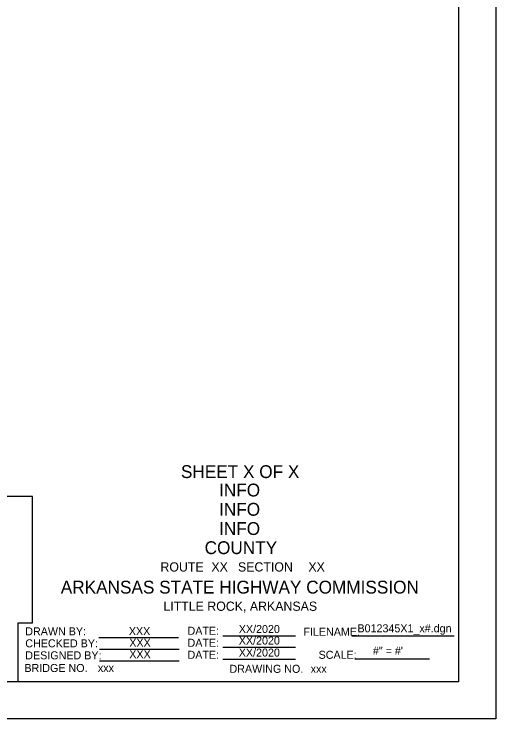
# Model space of a CAD drawing. Extents: x 16 to 1228740, y 11 to 152440.
# Drawn here: x 17.864 to 18.49, y 10.709 to 11.626 of the extents above; entities that cross this region are included whole.
import ezdxf

# ---------------------------------------------------------------- set-up
doc = ezdxf.new("R2010")
doc.units = 0
for name, color, linetype in [('B_Copy In', 7, 'Continuous'), ('B_County and Route', 7, 'Continuous'), ('B_Text', 7, 'Continuous'), ('B_Title Text', 7, 'Continuous'), ('R_Border', 7, 'Continuous'), ('R_No Plot', 7, 'Continuous')]:
    doc.layers.add(name, color=color, linetype=linetype)

msp = doc.modelspace()

# ---------------------------------------------------------------- linework, layer by layer
at = {"layer": 'B_Text'}
for p, q in [((18.13559, 10.81765), (18.23009, 10.81765)), ((18.30318, 10.81765), (18.43623, 10.81765)), ((17.97449, 10.81515), (18.07809, 10.81515)), ((17.97509, 10.80015), (18.07869, 10.80015)), ((18.13559, 10.80265), (18.23009, 10.80265)), ((18.13559, 10.80265), (18.23009, 10.80265)), ((17.97509, 10.78515), (18.07869, 10.78515)), ((18.13559, 10.78703), (18.23009, 10.78703)), ((18.30706, 10.78765), (18.40419, 10.78765))]:
    msp.add_line(p, q, dxfattribs=at)
at = {"layer": 'R_Border'}
for q in [(18.44221, 12.49475), (15.78327, 10.75755)]:
    msp.add_line((18.44221, 10.75755), q, dxfattribs=at)
msp.add_lwpolyline([(15.65694, 12.54282), (18.49027, 12.54282), (18.49027, 10.70949), (15.65694, 10.70949)], close=True, dxfattribs=at)
at = {"layer": 'R_No Plot'}
for p, q in [((17.888, 10.99864), (17.47349, 10.99864)), ((17.888, 10.83424), (17.888, 10.99864)), ((17.86946, 10.83424), (17.888, 10.83424)), ((17.86946, 10.75755), (17.86946, 10.83424))]:
    msp.add_line(p, q, dxfattribs=at)

# ---------------------------------------------------------------- texts
at = {"layer": 'B_Copy In'}
for s, height, p in [('SHEET X OF X', 0.0167, (18.08103, 11.02272)), ('INFO', 0.0167, (18.13057, 10.99878)), ('INFO', 0.0167, (18.13057, 10.97373)), ('INFO', 0.0167, (18.13057, 10.94868)), ('XXX', 0.0104, (18.01335, 10.81846)), ('XX/2020', 0.0104, (18.15625, 10.82119)), ('B012345X1_x#.dgn', 0.0104, (18.31045, 10.8221)), ('XX/2020', 0.0104, (18.15625, 10.80619)), ('XXX', 0.0104, (18.01395, 10.80346)), ('XXX', 0.0104, (18.01395, 10.78846)), ('XX/2020', 0.0104, (18.15625, 10.79057)), ('#" = #\'', 0.0104, (18.3305, 10.79302)), ('xxx', 0.010417, (17.97312, 10.7706)), ('xxx', 0.010417, (18.24962, 10.76944))]:
    msp.add_text(s, height=height, dxfattribs=at).set_placement(p)
at = {"layer": 'B_County and Route'}
for s, height, p in [('COUNTY', 0.0167, (18.11181, 10.92383)), ('XX', 0.012, (18.12061, 10.90115)), ('XX', 0.012, (18.24664, 10.90115))]:
    msp.add_text(s, height=height, dxfattribs=at).set_placement(p)
at = {"layer": 'B_Text'}
for s, height, p in [('DRAWN BY:', 0.010417, (17.87879, 10.8182)), ('DATE:', 0.010417, (18.08959, 10.8189)), ('FILENAME:', 0.010417, (18.24018, 10.81765)), ('CHECKED BY:', 0.0104166, (17.87879, 10.80257)), ('DATE:', 0.010417, (18.08959, 10.80328)), ('DESIGNED BY:', 0.0104166, (17.87879, 10.78695)), ('DATE:', 0.010417, (18.08959, 10.78765)), ('SCALE:', 0.010417, (18.25989, 10.78765)), ('BRIDGE NO.', 0.010417, (17.87767, 10.77048)), ('DRAWING NO.', 0.0104166, (18.14412, 10.76942))]:
    msp.add_text(s, height=height, dxfattribs=at).set_placement(p)
at = {"layer": 'B_Title Text'}
for s, height, p in [('ROUTE          SECTION ', 0.012, (18.0544, 10.90115)), ('ARKANSAS STATE HIGHWAY COMMISSION', 0.0167, (17.92492, 10.8725)), ('LITTLE ROCK, ARKANSAS', 0.012, (18.05823, 10.85007))]:
    msp.add_text(s, height=height, dxfattribs=at).set_placement(p)

doc.saveas('drawing.dxf')
